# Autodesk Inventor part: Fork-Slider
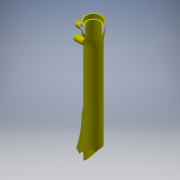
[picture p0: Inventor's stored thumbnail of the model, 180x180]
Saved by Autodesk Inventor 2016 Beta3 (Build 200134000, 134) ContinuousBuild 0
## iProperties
Shininess: 11.0
Length Units: 11272
Angle Units: 11279
Time Units: 11290
Mass Units: 11286
Length Display Precision: 3
Angle Display Precision: 2
Compacted: True
Created: 2001-11
Part Number: Fork-Slider
Document SubType Name: Modeling
Designer: Autodesk, Inc.
Mass: 115.049 g
Surface Area: 625.889 cm^2
Volume: 115.049 cm^3
Density: 1 g/cm^3
Material: Generic
Appearance: Yellow (Flat)
Density: 0.0
Volumn: 0.0
Area: 0.0
PropertySet Name: Model Information
Control State: 0
Master: False
Checked Out: False
Author: Autodesk, Inc.
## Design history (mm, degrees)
node "WorkPlane1"
node "WorkPlane2"
workplane "Work Plane3"
node "WorkPlane3"
sketch "Sketch1"
  geometry: L1 (-491.904, 893.583)-(-489.986, 893.583); L2 (-491.94, 890.889)-(-492.507, 891.195); L3 (-493.987, 888.502)-(-492.544, 888.502); L4 (-493.987, 883.604)-(-493.987, 888.502); L5 (-491.593, 861.235)-(-492.38, 865.605); L6 (-489.986, 628.153)-(-489.986, 843.237); L7 (-477.096, 614.183)-(-489.986, 628.153); L8 (-475.254, 614.183)-(-477.096, 614.183); L9 (-475.254, 630.693)-(-475.254, 614.183); L10 (-486.875, 630.693)-(-475.254, 630.693); L11 (-486.875, 883.423)-(-486.875, 630.693); L12 (-489.986, 883.423)-(-486.875, 883.423); L13 (-489.986, 893.583)-(-489.986, 883.423); L14 (-472.221, 864.964)-(-472.221, 656.569); L15 (-472.221, 864.964)-(-472.221, 656.569); A1 r 1.27 centre (-491.904, 892.313) between (-491.904, 893.583) and (-492.507, 891.195); A2 r 1.27 centre (-492.544, 889.772) between (-492.544, 888.502) and (-491.94, 890.889); A3 r 101.6 centre (-392.387, 883.604) between (-493.987, 883.604) and (-492.38, 865.605); A4 r 101.6 centre (-591.586, 843.237) between (-489.986, 843.237) and (-491.593, 861.235)
  constraints: 30 end point, 8 point on circle, 7 tangent, 6 vertical, 5 horizontal, 4 centre point, 1 collinear, 1 other
revolve "RevolutionFull1" sketch "Sketch1" stored, may be unused: angle "d2" = 360 deg
sketch "Sketch2"
  geometry: L1 (-468.069, 628.153)-(-489.986, 628.153); L2 (-468.069, 735.894)-(-468.069, 628.153); L3 (-450.045, 605.991)-(-450.045, 592.726); L4 (-458.808, 592.726)-(-458.808, 605.991); L5 (-467.317, 599.747)-(-465.345, 597.277); L6 (-489.986, 628.153)-(-467.317, 599.747); A1 r 136.444 centre (-590.87, 676.421) between (-454.426, 676.794) and (-468.069, 735.894); A2 r 273.047 centre (-182.07, 696.209) between (-454.426, 676.794) and (-440.731, 608.748); A3 r 13.97 centre (-454.426, 605.991) between (-450.045, 592.726) and (-440.731, 608.748); A4 r 4.382 centre (-454.426, 605.991) between (-450.045, 605.991) and (-458.808, 605.991); A5 r 13.97 centre (-454.426, 605.991) between (-465.345, 597.277) and (-458.808, 592.726)
  constraints: 12 end point, 10 point on circle, 5 centre point
extrude "ExtrusionBlind1" join sketch "Sketch2" distance "d3" = 9.652; taper "d4" = 0 deg
node "WorkAxis1"
workplane "Work Plane5"
workplane "Work Plane6"
node "WorkPlane4"
workplane "Work Plane8"
node "WorkPlane5"
sketch "Sketch3"
  geometry: L1 (0, -4.165)-(0, 0); L2 (9.652, -4.076)-(9.652, -4.165); L3 (0, -4.165)-(9.652, -4.165); A1 r 17.766 centre (11.43, 13.6) between (0, 0) and (9.652, -4.076)
  constraints: 6 end point, 2 point on circle, 1 centre point
extrude "ExtrusionThru1" cut sketch "Sketch3" stored distance "d17" = 3.302; taper "d18" = 0 deg
sketch "Sketch4"
  geometry: C1 r 14.654 at (14.546, 1.778)
  constraints: 1 centre point
extrude "ExtrusionThru2" cut sketch "Sketch4" stored distance "d19" = 3.302; taper "d20" = 0 deg
sketch "Sketch5"
  geometry: L1 (-458.808, 605.991)-(-458.808, 592.726) reference; L2 (-450.045, 592.726)-(-450.045, 605.991) reference; A1 r 4.382 centre (-454.426, 605.991) between (-450.045, 605.991) and (-458.808, 605.991) reference; A2 r 10.668 centre (-454.426, 605.991) between (-450.045, 596.265) and (-458.808, 596.265)
  constraints: 2 point on circle, 2 point on line, 1 centre point
extrude "ExtrusionBlind2" cut sketch "Sketch5" distance "d21" = 4.572; taper "d22" = 0 deg
sketch "Sketch6"
  geometry: C1 r 6.985 at (-100.202, 21.766)
  constraints: 1 centre point
extrude "ExtrusionBlind3" join sketch "Sketch6" distance "d23" = 20.32; taper "d24" = 0 deg
node "Sketch7"
sketch "Sketch8"
  geometry: L1 (-126.546, 21.766)-(-131.444, 21.766) reference; L2 (-106.924, 19.867)-(-104.178, 19.373) reference; L3 (-108.547, 20.159)-(-106.924, 19.867) reference; L4 (-131.444, 21.766)-(-126.546, 21.766) reference; L5 (-131.444, 20.323)-(-131.444, 21.766) reference; L6 (-134.137, 20.286)-(-133.831, 19.719) reference; L7 (-136.525, 17.766)-(-136.525, 19.683) reference; L8 (-126.365, 17.766)-(-136.525, 17.766) reference; L9 (-126.365, 14.654)-(-126.365, 17.766) reference; L10 (126.365, 14.654)-(-126.365, 14.654) reference; L11 (126.365, 1.587)-(126.365, 14.654) reference; L12 (135.255, 1.587)-(126.365, 1.587) reference; L13 (135.255, 3.034)-(135.255, 1.587) reference; L14 (151.166, 3.034)-(135.255, 3.034) reference; L15 (151.166, 11.43)-(151.166, 3.034) reference; L16 (135.771, 11.43)-(151.166, 11.43) reference; L17 (128.905, 17.766)-(135.771, 11.43) reference; L18 (-86.179, 17.766)-(128.905, 17.766) reference; L19 (-104.178, -19.373)-(-108.547, -20.159) reference; L20 (-126.546, -21.766)-(-131.444, -21.766) reference; L21 (-131.444, -21.766)-(-131.444, -20.323) reference; L22 (-133.831, -19.719)-(-134.137, -20.286) reference; L23 (-136.525, -19.683)-(-136.525, -17.766) reference; L24 (-136.525, -17.766)-(-126.365, -17.766) reference; L25 (-126.365, -17.766)-(-126.365, -14.654) reference; L26 (-126.365, -14.654)-(126.365, -14.654) reference; L27 (126.365, -14.654)-(126.365, -1.587) reference; L28 (126.365, -1.587)-(135.255, -1.587) reference; L29 (135.255, -1.587)-(135.255, -3.034) reference; L30 (135.255, -3.034)-(142.875, -3.034) reference; L31 (142.875, -3.034)-(142.875, -4.875) reference; L32 (142.875, -4.875)-(128.905, -17.766) reference; L33 (128.905, -17.766)-(-86.179, -17.766) reference; C1 r 6.35 at (-124.333, 15.39); A1 r 6.985 centre (-100.202, 21.766) between (-94.264, 18.088) and (-106.924, 19.867) reference; A2 r 101.6 centre (-86.179, 119.366) between (-104.178, 19.373) and (-94.264, 18.088) reference; A3 r 101.6 centre (-126.546, -79.834) between (-108.547, 20.159) and (-123.263, 21.713) reference; A4 r 101.6 centre (-126.546, -79.834) between (-125.109, 21.756) and (-126.546, 21.766) reference; A5 r 1.27 centre (-132.714, 20.323) between (-133.831, 19.719) and (-131.444, 20.323) reference; A6 r 1.27 centre (-135.255, 19.683) between (-134.137, 20.286) and (-136.525, 19.683) reference; A7 r 101.6 centre (-86.179, 119.366) between (-94.264, 18.088) and (-86.179, 17.766) reference; A8 r 101.6 centre (-126.546, -79.834) between (-123.263, 21.713) and (-125.109, 21.756) reference; A9 r 101.6 centre (-86.179, -119.366) between (-86.179, -17.766) and (-104.178, -19.373) reference; A10 r 101.6 centre (-126.546, 79.834) between (-126.546, -21.766) and (-108.547, -20.159) reference; A11 r 1.27 centre (-132.714, -20.323) between (-131.444, -20.323) and (-133.831, -19.719) reference; A12 r 1.27 centre (-135.255, -19.683) between (-136.525, -19.683) and (-134.137, -20.286) reference
  constraints: 1 centre point, 1 tangent
extrude "ExtrusionBlind4" join sketch "Sketch8" distance "d26" = 23.368; taper "d27" = 0 deg
node "Sketch9"
extrude "ExtrusionToPlane1" cut stored distance "d29" = 3.302; taper "d30" = 0 deg
  node "Sketch10"
extrude "ExtrusionBlind5" cut distance "d31" = 50.8; taper "d32" = 0 deg
  node "Sketch11"
workplane "Work Plane10"
sketch "Sketch13"
  geometry: C1 r 3.034 at (0, 0); A1 r 3.034 centre (0, 0) between (-2.458, 1.778) and (2.458, 1.778) reference
  constraints: 1 centre point, 1 coincident, 1 concentric
workplane "Work Plane11"
extrude "Extrusion9" join sketch "Sketch13" stored distance "d34" = 25.4; taper "d35" = 0 deg
sketch "Sketch14"
  geometry: L1 (-2.458, 1.778)-(2.458, 1.778) reference; C1 r 3.034 at (0, 0); A1 r 3.034 centre (0, 0) between (-2.458, 1.778) and (2.458, 1.778) reference
  constraints: 1 centre point, 1 coincident, 1 concentric
extrude "Extrusion10" cut sketch "Sketch14" stored distance "d36" = 25.4; taper "d37" = 0 deg
sketch "Sketch15"
  geometry: C1 r 3.034 at (0, 0) reference
hole "Hole1" sketch "Sketch15" at (0, 0) diameter "d38" = 3.175; stored, may be unused: countersink angle "d42" = 82 deg, drill point angle "d44" = 118 deg; dims "d39" = 12.7, "d40" = 9.525, "d41" = 6.35, "d43" = 19.05
sketch "Sketch16"
  geometry: C1 r 6.985 at (0, 0) reference
hole "Hole2" sketch "Sketch16" at (0, 0) diameter "d45" = 4.3434; stored, may be unused: countersink angle "d49" = 82 deg, drill point angle "d51" = 118 deg; dims "d46" = 12.7, "d47" = 9.525, "d48" = 6.35, "d50" = 12.7
sketch "Sketch17"
  geometry: C1 r 6.35 at (0, 0) reference
hole "Hole3" sketch "Sketch17" at (0, 0) diameter "d52" = 3.2512; stored, may be unused: countersink angle "d56" = 82 deg, drill point angle "d58" = 118 deg; dims "d53" = 12.7, "d54" = 9.525, "d55" = 6.35, "d57" = 12.7
body "Solid1"
other parameters: "d0" = -11.43, "d1" = -19.05, "d5" = 0, "d6" = 0, "d7" = 0, "d8" = 0, "d9" = 0, "d10" = 0, "d11" = 0, "d12" = 0, "d13" = 0, "d14" = 0, "d15" = 0, "d16" = 0, "d25" = 0, "d28" = 0, "d33" = -7.62
